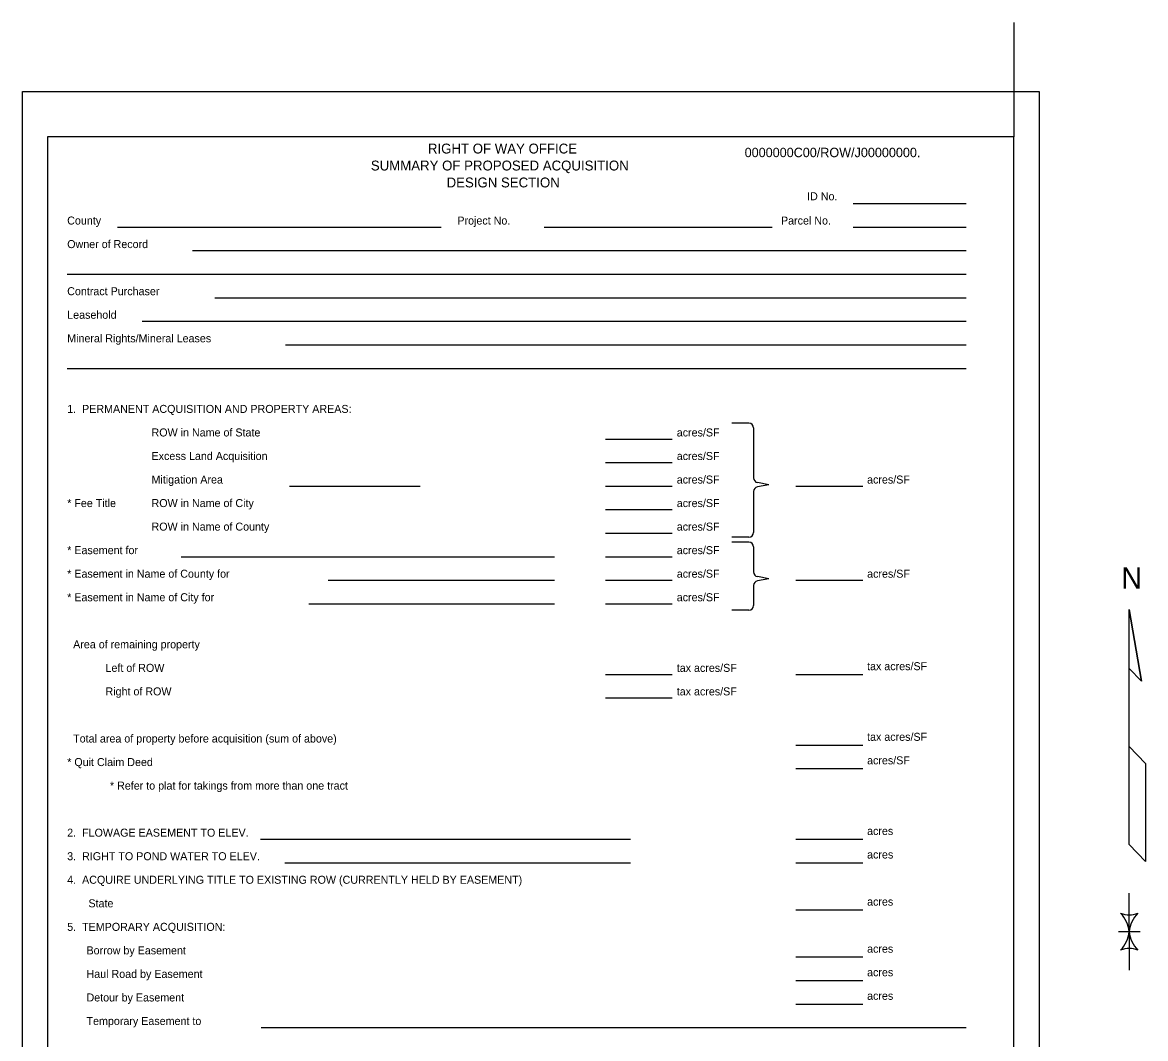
# Model space of a CAD drawing. Extents: x -64422 to -63705, y -154995 to -154568.
# Drawn here: x -64421.9 to -64185.8, y -154782 to -154568.3 of the extents above; entities that cross this region are included whole.
import ezdxf

# ---------------------------------------------------------------- set-up
doc = ezdxf.new("R2010")
doc.units = 0
for name, color, linetype in [('rowdsnPSConstructPlot', 7, 'Continuous'), ('rowdsnPSSummary', 7, 'Continuous'), ('rowdsnSymbolsOther', 7, 'Continuous'), ('rowdsnSymbolsPL', 7, 'Continuous')]:
    doc.layers.add(name, color=color, linetype=linetype)

msp = doc.modelspace()

# ---------------------------------------------------------------- linework, layer by layer
at = {"layer": 'rowdsnPSConstructPlot'}
msp.add_lwpolyline([(-64213.43, -154592.36), (-64416.63, -154592.36), (-64416.63, -154932.55), (-64213.43, -154932.55)], close=True, dxfattribs=at)
at = {"layer": 'rowdsnPSSummary'}
for p, q in [((-64213.43, -154568.3), (-64213.43, -154592.36)), ((-64213.43, -154568.3), (-64213.43, -154592.36)), ((-64421.91, -154934.87), (-64421.91, -154582.8)), ((-64421.91, -154582.8), (-64208.15, -154582.8)), ((-64208.15, -154582.8), (-64208.15, -154934.87)), ((-64223.47, -154606.46), (-64247.22, -154606.46)), ((-64333.9, -154611.41), (-64401.95, -154611.41)), ((-64264.28, -154611.41), (-64312.22, -154611.41)), ((-64223.47, -154611.41), (-64247.22, -154611.41)), ((-64223.47, -154616.36), (-64386.16, -154616.36)), ((-64223.47, -154621.31), (-64412.5, -154621.31)), ((-64223.47, -154626.26), (-64381.47, -154626.26)), ((-64223.47, -154631.21), (-64396.73, -154631.21)), ((-64223.47, -154636.16), (-64366.6, -154636.16)), ((-64223.47, -154641.12), (-64412.5, -154641.12)), ((-64269.15, -154652.58), (-64272.72, -154652.58)), ((-64268.16, -154653.57), (-64268.16, -154664.09)), ((-64285.27, -154655.97), (-64299.31, -154655.97)), ((-64285.27, -154660.92), (-64299.31, -154660.92)), ((-64338.29, -154665.87), (-64365.74, -154665.87)), ((-64285.27, -154665.87), (-64299.31, -154665.87)), ((-64268.16, -154666.93), (-64268.16, -154675.55)), ((-64264.94, -154665.51), (-64267.35, -154665.07)), ((-64264.94, -154665.51), (-64267.35, -154665.96)), ((-64245.22, -154665.87), (-64259.26, -154665.87)), ((-64285.27, -154670.82), (-64299.31, -154670.82)), ((-64285.27, -154675.77), (-64299.31, -154675.77)), ((-64269.15, -154676.54), (-64272.72, -154676.54)), ((-64269.15, -154677.58), (-64272.72, -154677.58)), ((-64268.16, -154678.57), (-64268.16, -154683.86)), ((-64310.07, -154680.72), (-64388.51, -154680.72)), ((-64285.27, -154680.72), (-64299.31, -154680.72)), ((-64310.07, -154685.67), (-64357.6, -154685.67)), ((-64285.27, -154685.67), (-64299.31, -154685.67)), ((-64264.94, -154685.29), (-64267.35, -154684.84)), ((-64264.94, -154685.29), (-64267.35, -154685.73)), ((-64245.22, -154685.67), (-64259.26, -154685.67)), ((-64268.16, -154686.7), (-64268.16, -154690.92)), ((-64310.07, -154690.62), (-64361.71, -154690.62)), ((-64285.27, -154690.62), (-64299.31, -154690.62)), ((-64269.15, -154691.91), (-64272.72, -154691.91)), ((-64285.27, -154705.47), (-64299.31, -154705.47)), ((-64245.22, -154705.47), (-64259.26, -154705.47)), ((-64285.27, -154710.42), (-64299.31, -154710.42)), ((-64245.22, -154720.32), (-64259.26, -154720.32)), ((-64245.22, -154725.27), (-64259.26, -154725.27)), ((-64294.03, -154740.13), (-64371.88, -154740.13)), ((-64245.22, -154740.13), (-64259.26, -154740.13)), ((-64294.03, -154745.08), (-64366.73, -154745.08)), ((-64319.85, -154745.08), (-64360.15, -154745.08)), ((-64245.22, -154745.08), (-64259.26, -154745.08)), ((-64245.22, -154754.98), (-64259.26, -154754.98)), ((-64245.22, -154764.88), (-64259.26, -154764.88)), ((-64245.22, -154769.83), (-64259.26, -154769.83)), ((-64245.22, -154774.78), (-64259.26, -154774.78)), ((-64223.47, -154779.73), (-64371.69, -154779.73))]:
    msp.add_line(p, q, dxfattribs=at)
for centre, start, end in [((-64269.15, -154653.57), 0, 90), ((-64267.17, -154664.09), 180, 259.4341), ((-64267.17, -154666.93), 100.4742, 180), ((-64269.15, -154675.55), 270, 0), ((-64269.15, -154678.57), 0, 90), ((-64267.17, -154683.86), 180, 259.6375), ((-64267.17, -154686.71), 100.5327, 180), ((-64269.15, -154690.92), 270, 0)]:
    msp.add_arc(centre, 0.99, start, end, dxfattribs=at)
at = {"layer": 'rowdsnSymbolsOther'}
for p, q in [((-64189.19, -154741.16), (-64189.19, -154691.78)), ((-64186.61, -154706.79), (-64189.19, -154691.78)), ((-64189.19, -154704.13), (-64186.61, -154706.79)), ((-64189.19, -154720.59), (-64185.76, -154724.14)), ((-64185.76, -154724.14), (-64185.76, -154744.71)), ((-64189.19, -154741.16), (-64185.76, -154744.71))]:
    msp.add_line(p, q, dxfattribs=at)
for points in [[(-64189.19, -154691.78), (-64186.61, -154706.79), (-64189.19, -154704.13)], [(-64189.19, -154720.59), (-64185.76, -154724.14), (-64185.76, -154744.71), (-64189.19, -154741.16)]]:
    msp.add_lwpolyline(points, close=True, dxfattribs=at)
at = {"layer": 'rowdsnSymbolsPL'}
for p, q in [((-64189.19, -154759.49), (-64189.19, -154751.41)), ((-64191.47, -154759.49), (-64186.9, -154759.49)), ((-64189.19, -154759.49), (-64189.19, -154767.57))]:
    msp.add_line(p, q, dxfattribs=at)
for centre, radius, start, end in [((-64195.74, -154760.19), 6.59, 6.1059, 43.9131), ((-64189.19, -154750.82), 5.13, 249.3932, 290.6068), ((-64182.64, -154760.19), 6.59, 136.0869, 173.8941), ((-64195.74, -154758.79), 6.59, 316.0869, 353.8941), ((-64182.64, -154758.79), 6.59, 186.1059, 223.9131), ((-64189.19, -154768.16), 5.13, 69.3932, 110.6068)]:
    msp.add_arc(centre, radius, start, end, dxfattribs=at)

# ---------------------------------------------------------------- texts
at = {"layer": 'rowdsnPSSummary'}
for s, height, p in [('RIGHT OF WAY OFFICE', 2.0792, (-64336.65, -154595.86)), ('0000000C00/ROW/J00000000. ', 1.9802, (-64270.05, -154596.63)), ('SUMMARY OF PROPOSED ACQUISITION', 2.0792, (-64348.65, -154599.43)), ('DESIGN SECTION', 2.0792, (-64332.72, -154602.99)), ('ID No.', 1.683, (-64256.92, -154605.69)), ('County', 1.683, (-64412.5, -154610.8)), ('Project No.', 1.6832, (-64330.46, -154610.8)), ('Parcel No.', 1.683, (-64262.41, -154610.8)), ('Owner of Record', 1.6832, (-64412.5, -154615.75)), ('Contract Purchaser', 1.6832, (-64412.5, -154625.66)), ('Leasehold', 1.683, (-64412.5, -154630.61)), ('Mineral Rights/Mineral Leases', 1.6832, (-64412.5, -154635.56)), ('1.  PERMANENT ACQUISITION AND PROPERTY AREAS:', 1.6832, (-64412.5, -154650.41)), ('ROW in Name of State', 1.6832, (-64394.77, -154655.36)), ('acres/SF', 1.683, (-64284.33, -154655.36)), ('Excess Land Acquisition', 1.6832, (-64394.77, -154660.31)), ('acres/SF', 1.683, (-64284.33, -154660.31)), ('Mitigation Area', 1.6832, (-64394.77, -154665.26)), ('acres/SF', 1.683, (-64284.33, -154665.26)), ('acres/SF', 1.683, (-64244.31, -154665.26)), ('* Fee Title', 1.6832, (-64412.5, -154670.21)), ('ROW in Name of City', 1.6832, (-64394.77, -154670.21)), ('acres/SF', 1.683, (-64284.33, -154670.21)), ('ROW in Name of County', 1.6832, (-64394.77, -154675.16)), ('acres/SF', 1.683, (-64284.33, -154675.16)), ('* Easement for', 1.6832, (-64412.5, -154680.11)), ('acres/SF', 1.683, (-64284.33, -154680.11)), ('* Easement in Name of County for', 1.6832, (-64412.5, -154685.06)), ('acres/SF', 1.683, (-64284.33, -154685.06)), ('acres/SF', 1.683, (-64244.3, -154685.06)), ('* Easement in Name of City for', 1.6832, (-64412.5, -154690.01)), ('acres/SF', 1.683, (-64284.33, -154690.01)), ('  Area of remaining property', 1.6832, (-64412.5, -154699.91)), ('  Left of ROW', 1.6832, (-64405.7, -154704.86)), ('tax acres/SF', 1.6832, (-64284.33, -154704.86)), ('tax acres/SF', 1.6832, (-64244.31, -154704.51)), ('  Right of ROW', 1.6832, (-64405.7, -154709.81)), ('tax acres/SF', 1.6832, (-64284.33, -154709.81)), ('  Total area of property before acquisition (sum of above)', 1.6832, (-64412.5, -154719.72)), ('tax acres/SF', 1.6832, (-64244.31, -154719.36)), ('* Quit Claim Deed', 1.6832, (-64412.5, -154724.67)), ('acres/SF', 1.683, (-64244.31, -154724.31)), ('* Refer to plat for takings from more than one tract', 1.6832, (-64403.51, -154729.62)), ('2.  FLOWAGE EASEMENT TO ELEV.', 1.6832, (-64412.5, -154739.52)), ('acres', 1.683, (-64244.31, -154739.16)), ('3.  RIGHT TO POND WATER TO ELEV.', 1.6832, (-64412.5, -154744.47)), ('acres', 1.683, (-64244.31, -154744.11)), ('4.  ACQUIRE UNDERLYING TITLE TO EXISTING ROW (CURRENTLY HELD BY EASEMENT)', 1.6832, (-64412.5, -154749.42)), ('State', 1.683, (-64408.04, -154754.37)), ('acres', 1.683, (-64244.31, -154754.02)), ('5.  TEMPORARY ACQUISITION:', 1.6832, (-64412.5, -154759.32)), ('Borrow by Easement', 1.6832, (-64408.44, -154764.27)), ('acres', 1.683, (-64244.31, -154763.92)), ('Haul Road by Easement', 1.6832, (-64408.44, -154769.22)), ('acres', 1.683, (-64244.31, -154768.87)), ('Detour by Easement', 1.6832, (-64408.44, -154774.17)), ('acres', 1.683, (-64244.31, -154773.82)), ('Temporary Easement to', 1.6832, (-64408.44, -154779.12))]:
    msp.add_text(s, height=height, dxfattribs=at).set_placement(p)
at = {"layer": 'rowdsnSymbolsOther'}
msp.add_text('N', height=4.5, dxfattribs=at).set_placement((-64190.85, -154687.36))

doc.saveas('drawing.dxf')
